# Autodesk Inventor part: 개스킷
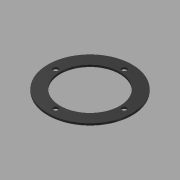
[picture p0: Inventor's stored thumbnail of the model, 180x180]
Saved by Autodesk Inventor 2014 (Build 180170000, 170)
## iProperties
Created: 2018-06
Part Number: 개스킷
Material: 고무
Document SubType Name: Modeling
Designer: G4400
Density: 0.93 g/cm^3
Appearance: 고무 - 검은색 - 버전 1.1
Mass: 2.24056 g
Surface Area: 38.1075 cm^2
Volume: 2.40921 cm^3
Author: G4400
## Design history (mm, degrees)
sketch "스케치1"
  geometry: C1 r 32.5 at (0, 0); C2 r 23 at (0, 0); 1 further point
  constraints: 2 centre point, 2 coincident
  dimensions: "d0" = 65 diameter of C1; "d1" = 46 diameter of C2
extrude "돌출1" new body sketch "스케치1" distance "d2" = 1.5; taper "d3" = 0 deg
sketch "스케치2" dims "d5" = 26.5
  geometry: C1 r 23 at (0, 0) reference; C2 r 32.5 at (0, 0) reference; 5 further points
  constraints: 2 vertical alignment, 1 coincident, 7 other
  dimensions: "d9" = 360 deg dimension on C1.centre point (0, 26.5) (derived)
hole "구멍1" sketch "스케치2" at (0, 26.5), (-26.5, 0), (0, -26.5), (26.5, 0) diameter "d11" = 4; stored, may be unused: countersink angle "d15" = 90 deg, drill point angle "d17" = 118 deg; dims "d12" = 6, "d13" = 4, "d14" = 2, "d16" = 8
node "솔리드1"
